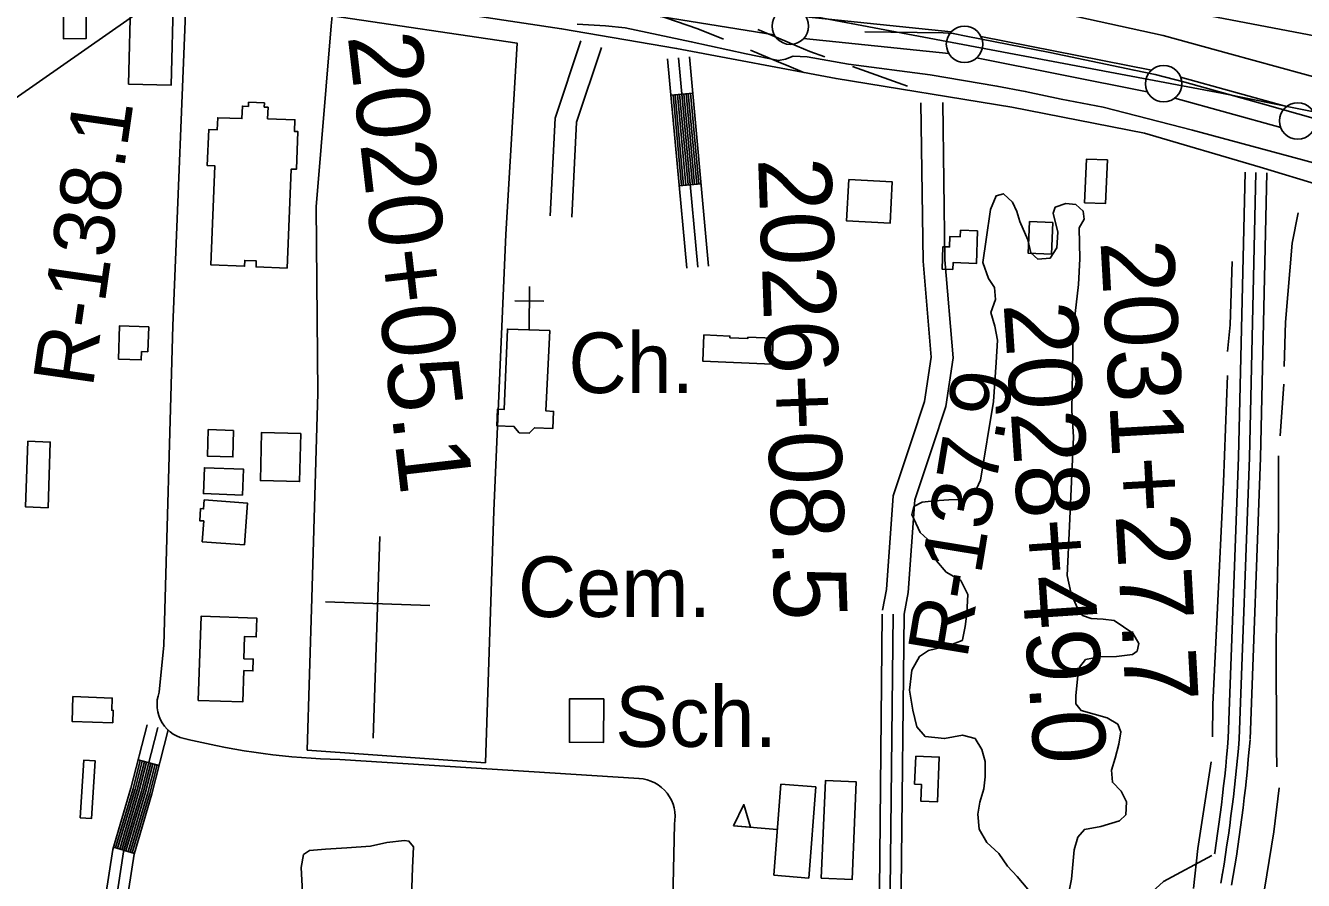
# Model space of a CAD drawing. Extents: x 3508733 to 3546731, y 546897 to 572481.
# Drawn here: x 3525316 to 3527070, y 561862 to 563035 of the extents above; entities that cross this region are included whole.
import ezdxf

# ---------------------------------------------------------------- set-up
doc = ezdxf.new("R2010")
doc.units = 0
for name, color, linetype in [('V-BLDG-IDEN', 7, 'Continuous'), ('V-BLDG-OTLN', 7, 'Continuous'), ('V-FLOD-BASE', 7, 'Continuous'), ('V-LEVE-TOET', 7, 'Continuous'), ('V-RIVR-FERY', 7, 'Continuous'), ('V-RIVR-RANG-IDEN', 7, 'Continuous'), ('V-ROAD-CNTR', 7, 'Continuous'), ('V-RRAP-FSHR', 7, 'Continuous'), ('V-SITE-OTLN', 7, 'Continuous'), ('V-SITE-OTLN-IDEN', 7, 'Continuous'), ('V-SITE-VEGE', 7, 'Continuous'), ('V-SURV-IDEN', 7, 'Continuous'), ('V-SURV-LINE', 7, 'Continuous'), ('V-TOPO-MINR', 7, 'Continuous'), ('V-TOPO-SHOR', 7, 'Continuous')]:
    doc.layers.add(name, color=color, linetype=linetype)

msp = doc.modelspace()

# ---------------------------------------------------------------- linework, layer by layer
at = {"layer": 'V-BLDG-OTLN'}
msp.add_line((3526347.4, 561932.5), (3526287.6, 561937.4), dxfattribs=at)
for points in [[(3525398.1, 563093.9), (3525398.9, 563017.6), (3525367.5, 563017.3), (3525367.4, 563093.6)], [(3525456.8, 562955.1), (3525459.9, 563080.7), (3525518.7, 563079.2), (3525515.6, 562953.7)], [(3525674.6, 562702.5), (3525632, 562704.2), (3525632.3, 562712.4), (3525616.4, 562713.1), (3525616.1, 562705.1), (3525570, 562706.9), (3525575.4, 562842.8), (3525565, 562843.2), (3525567, 562892.7), (3525578.6, 562892.3), (3525579.3, 562908.9), (3525612.6, 562907.6), (3525613.3, 562924.8), (3525621.5, 562924.5), (3525621.8, 562930.2), (3525643.5, 562929.3), (3525643.2, 562923.4), (3525648.4, 562923.2), (3525647.8, 562907.5), (3525685.4, 562906), (3525684.7, 562890), (3525689.4, 562889.8), (3525687.3, 562838.1), (3525680.1, 562838.3)], [(3526800.7, 562851), (3526798, 562791), (3526769.5, 562792.3), (3526772.2, 562852.2)], [(3526445.7, 562824.1), (3526505.4, 562820.9), (3526502.4, 562764), (3526442.7, 562767.2)], [(3526694, 562766.4), (3526725.8, 562765.1), (3526723.9, 562721.6), (3526692.1, 562722.9)], [(3526622.6, 562753.6), (3526621.1, 562709), (3526588.8, 562710.1), (3526588.5, 562700.7), (3526573.8, 562701.2), (3526574.9, 562731.9), (3526584.1, 562731.6), (3526584.6, 562746.1), (3526598.8, 562745.6), (3526599.1, 562754.4)], [(3525442.9, 562577.7), (3525444.7, 562623.4), (3525484.6, 562621.9), (3525483.3, 562587.7), (3525474.7, 562588.1), (3525474.3, 562576.5)], [(3526035.2, 562616.9), (3526030, 562506.5), (3526040.4, 562506), (3526039.3, 562482.3), (3526014, 562483.5), (3526007.1, 562475.9), (3525993.3, 562476.7), (3525986, 562485.4), (3525962.5, 562486.2), (3525963.4, 562509), (3525972.8, 562508.7), (3525977, 562618.9)], [(3526340.3, 562570.6), (3526245.1, 562574.9), (3526246.8, 562610.9), (3526282.6, 562609.3), (3526282.5, 562606.9), (3526307, 562605.8), (3526307.1, 562607.7), (3526341.9, 562606.2)], [(3525601.2, 562479.9), (3525600.1, 562443.4), (3525565.3, 562444.5), (3525566.4, 562481)], [(3525346.4, 562373.8), (3525315.6, 562374.8), (3525318.7, 562465), (3525349.5, 562463.9)], [(3525693.4, 562475.6), (3525691.7, 562409.6), (3525637.9, 562411), (3525639.6, 562477)], [(3525613.4, 562391.1), (3525559.7, 562393.2), (3525561.1, 562428.7), (3525614.8, 562426.6)], [(3525616.1, 562323), (3525558, 562327.2), (3525560.1, 562355.6), (3525554.7, 562356), (3525555.9, 562372.5), (3525559.9, 562372.2), (3525560.8, 562384.5), (3525620.2, 562380.2)], [(3525552.5, 562109.5), (3525556.5, 562224.9), (3525633.2, 562222.2), (3525632.3, 562196.6), (3525616.3, 562197.1), (3525615.3, 562166.6), (3525628.2, 562166.1), (3525627.6, 562149.8), (3525615.3, 562150.3), (3525613.8, 562107.4)], [(3525435.3, 562078.5), (3525379.3, 562080.6), (3525380.6, 562114.6), (3525434.5, 562112.6), (3525433.9, 562095.8), (3525435.9, 562095.7)], [(3526109.2, 562111.6), (3526109.1, 562051.8), (3526062.2, 562051.9), (3526062.3, 562111.7)], [(3525390.3, 561948.3), (3525395.5, 562027.3), (3525411.1, 562026.3), (3525405.9, 561947.2)], [(3526537.6, 562033.1), (3526569.9, 562031.7), (3526567.3, 561970.2), (3526544.4, 561971.2), (3526545.4, 561994.2), (3526536, 561994.6)], [(3526342.7, 561869.4), (3526352.4, 561994.4), (3526400.4, 561990.7), (3526390.8, 561865.7)], [(3526407.9, 561865.3), (3526413.6, 561999.3), (3526455.9, 561997.5), (3526450.2, 561863.5)], [(3526287.6, 561937.4), (3526301.5, 561966.4), (3526310.6, 561935.5)]]:
    msp.add_lwpolyline(points, close=True, dxfattribs=at)
at = {"layer": 'V-FLOD-BASE'}
msp.add_lwpolyline([(3527162.6, 562885.9), (3527013.7, 562927.8), (3526907.1, 562957.7), (3526866.1, 562968.4), (3526837.3, 562974.1), (3526721.8, 562998.6), (3526606.9, 563021), (3526589.1, 563024.6), (3526575.4, 563025.5), (3526467.8, 563026.6)], dxfattribs=at)
at = {"layer": 'V-LEVE-TOET'}
for points in [[(3526716.1, 563056.9), (3526877.5, 563021.7), (3526969, 562996.7), (3527068.8, 562969), (3527161.7, 562944.1)], [(3527188.4, 562818.6), (3527051.7, 562855.6), (3526917.7, 562892), (3526794.7, 562923.4), (3526737.3, 562934.2), (3526688, 562945), (3526649, 562952.2), (3526557.4, 562967.6), (3526445.1, 562982.4), (3526388.4, 562992.6), (3526369.1, 562993.3), (3526358.8, 562989.3), (3526349.2, 562987.4), (3526304.7, 562996.7), (3526229.5, 563013.2), (3526138.6, 563032), (3526111.9, 563035), (3526072.8, 563037.4)]]:
    msp.add_lwpolyline(points, dxfattribs=at)
at = {"layer": 'V-RIVR-FERY'}
msp.add_lwpolyline([(3524970.1, 562704.4), (3528560.1, 565210.4)], dxfattribs=at)
at = {"layer": 'V-ROAD-CNTR'}
for p, q in [((3526450.7, 562979.3), (3526526.1, 562952.2)), ((3526231.4, 562942.7), (3526201.5, 562940)), ((3526242.9, 562818.3), (3526213, 562815.5)), ((3525499.1, 562020.3), (3525470, 562027.7)), ((3525464.9, 561899.5), (3525436.2, 561908))]:
    msp.add_line(p, q, dxfattribs=at)
for points in [[(3527459.7, 562715.9), (3527179.9, 562790), (3527010.3, 562841.2), (3526851.7, 562887.6), (3526669.4, 562923.3), (3526428.3, 562962.7), (3526209.3, 563003.9), (3526051.5, 563030.9), (3525817.1, 563066.2), (3525532, 563111)], [(3525537.4, 563109.3), (3525517.5, 562623.4), (3525505.4, 562185.3), (3525498.9, 562120.6)], [(3526180, 563051), (3526238.5, 563030.7), (3526273.9, 563016.8)], [(3526320.6, 563030.1), (3526358, 563014.3), (3526374.9, 563007.1), (3526392.4, 562999.7), (3526413, 562992.6)], [(3526077.6, 563014.5), (3526042.4, 562908.3), (3526035.5, 562774.1)], [(3526106.1, 563005.1), (3526072.1, 562902.7), (3526065.5, 562772.5)], [(3526196.9, 562989.8), (3526223.4, 562702.6)], [(3526211.9, 562991.1), (3526238.4, 562704)], [(3526226.8, 562992.5), (3526253.3, 562705.3)], [(3526310.7, 563001.7), (3526346.4, 562986.6), (3526363.2, 562979.5), (3526381.6, 562971.7), (3526383.3, 562971.1)], [(3526204.5, 562940.2), (3526216, 562815.8)], [(3526207.5, 562940.5), (3526219, 562816.1)], [(3526210.5, 562940.8), (3526222, 562816.3)], [(3526213.5, 562941.1), (3526225, 562816.6)], [(3526216.5, 562941.4), (3526227.9, 562816.9)], [(3526219.4, 562941.6), (3526230.9, 562817.2)], [(3526222.4, 562941.9), (3526233.9, 562817.4)], [(3526225.4, 562942.2), (3526236.9, 562817.7)], [(3526228.4, 562942.5), (3526239.9, 562818)], [(3526544.8, 562929.4), (3526547.6, 562712.2), (3526559, 562580.3), (3526549.5, 562519.7), (3526531.6, 562465.4), (3526506.6, 562390.3), (3526497.4, 562261.4), (3526492, 562233.2)], [(3526574.8, 562929.8), (3526577.6, 562713.7), (3526589.2, 562579.3), (3526578.8, 562512.6), (3526560.1, 562456), (3526536.3, 562384.4), (3526527.2, 562257.6), (3526521.5, 562227.6)], [(3526989.7, 562834.1), (3526980.7, 562443), (3526966.6, 562057.3)], [(3527004.7, 562833.7), (3526995.7, 562442.5), (3526981.6, 562056.8)], [(3527019.7, 562833.4), (3527010.7, 562442.1), (3526996.6, 562056.2)], [(3526491.5, 562227.9), (3526487.7, 561848.4), (3526504.1, 561755.6), (3526479.9, 561326.3), (3526670.3, 561312.4), (3526693.8, 561308.9), (3526712.1, 561293.8)], [(3526506.5, 562227.8), (3526502.7, 561849.6), (3526519.2, 561756.5), (3526495.7, 561340.2), (3526671.9, 561327.3), (3526700.2, 561323.1), (3526731, 561297.6)], [(3526521.5, 562227.6), (3526517.7, 561850.9), (3526534.3, 561757.4), (3526511.5, 561354), (3526614.1, 561346.5)], [(3525482.3, 562076.1), (3525460.2, 561988.9), (3525435.3, 561905), (3525420.2, 561807.5), (3525409.2, 561645.6), (3525392, 561184.9), (3525372.2, 560681.9), (3525357.6, 560233.9)], [(3525496.9, 562072.4), (3525474.6, 561985), (3525449.9, 561901.7), (3525435.2, 561805.8), (3525424.1, 561644.8), (3525407, 561184.4), (3525387.1, 560681.4), (3525372.6, 560233.4)], [(3525511.4, 562068.8), (3525489.1, 561981), (3525464.6, 561898.4), (3525450.1, 561804.2), (3525439.1, 561644), (3525422, 561183.8), (3525402.1, 560680.8), (3525387.6, 560232.9)], [(3526966.7, 562058), (3526965.6, 562044.8), (3526964.4, 562031.6), (3526963.1, 562018.5), (3526961.8, 562005.3), (3526960.3, 561992.2), (3526958.8, 561979), (3526957.2, 561965.9), (3526955.6, 561952.8), (3526953.8, 561939.7), (3526952, 561926.6), (3526950.1, 561913.5), (3526948.1, 561900.4), (3526947.9, 561899.1)], [(3526981.6, 562056.8), (3526980.5, 562043.5), (3526979.3, 562030.2), (3526978, 562017), (3526976.7, 562003.7), (3526975.2, 561990.5), (3526973.7, 561977.3), (3526972.1, 561964), (3526970.4, 561950.8), (3526968.7, 561937.6), (3526966.8, 561924.4), (3526964.9, 561911.3), (3526962.9, 561898.1), (3526960.9, 561884.9), (3526958.7, 561871.8), (3526956.5, 561858.7)], [(3526996.6, 562055.5), (3526995.4, 562042.2), (3526994.2, 562028.8), (3526993, 562015.5), (3526991.6, 562002.2), (3526990.1, 561988.8), (3526988.6, 561975.5), (3526987, 561962.2), (3526985.3, 561948.9), (3526983.5, 561935.6), (3526981.7, 561922.3), (3526979.8, 561909.1), (3526977.8, 561895.8), (3526975.7, 561882.6), (3526973.5, 561869.3), (3526971.3, 561856.1)], [(3525472.9, 562026.9), (3525463.1, 561988.2), (3525439, 561907.1)], [(3525475.8, 562026.2), (3525466, 561987.4), (3525441.9, 561906.3)], [(3525478.7, 562025.5), (3525468.9, 561986.6), (3525444.8, 561905.4)], [(3525481.6, 562024.7), (3525471.7, 561985.8), (3525447.7, 561904.6)], [(3525484.6, 562024), (3525474.6, 561985), (3525450.5, 561903.7)], [(3525487.5, 562023.3), (3525477.5, 561984.2), (3525453.4, 561902.9)], [(3525490.4, 562022.5), (3525480.4, 561983.4), (3525456.3, 561902)], [(3525747, 562028.3), (3526157.7, 562002.2)], [(3525493.3, 562021.8), (3525483.3, 561982.6), (3525459.2, 561901.2)], [(3525496.2, 562021), (3525486.2, 561981.8), (3525462.1, 561900.3)], [(3526206.2, 561939.5), (3526193.4, 561358.8), (3526177.8, 560724.9)], [(3526944, 561896.4), (3526877.9, 561860.9), (3526811.7, 561801.2), (3526762.1, 561734.8), (3526714.7, 561611.5), (3526705.7, 561513.1), (3526695.2, 561438.9), (3526666.7, 561400.7), (3526616.3, 561347.6)], [(3526958.2, 561870), (3526957.2, 561869.4)]]:
    msp.add_lwpolyline(points, dxfattribs=at)
for centre, radius, start, end in [((3525544.3, 562103.9), 48.3, 159.7838, 263.1784), ((3525771.3, 563013.2), 985.2, 256.3192, 268.5851), ((3526154.9, 561949.9), 52.4, 348.4996, 86.9598)]:
    msp.add_arc(centre, radius, start, end, dxfattribs=at)
at = {"layer": 'V-RRAP-FSHR'}
msp.add_lwpolyline([(3523475.5, 563626.1), (3524086.4, 563502.4), (3525193.3, 563274.6), (3526957.5, 562942.6), (3528202.6, 562690.4), (3529085.9, 562552.3), (3529836.5, 562463.4), (3529988.5, 562444.1), (3530121.4, 562433.3), (3530591.9, 562422.1), (3531229.9, 562384.2)], dxfattribs=at)
at = {"layer": 'V-SITE-OTLN'}
for p, q in [((3526006.7, 562617.4), (3526007.2, 562677.4)), ((3526027, 562657.3), (3525987, 562657.6)), ((3525792.7, 562057.8), (3525802.1, 562334.5)), ((3525870.5, 562239.8), (3525727.5, 562244.7))]:
    msp.add_line(p, q, dxfattribs=at)
msp.add_lwpolyline([(3525734.9, 563034.9), (3525736.4, 563048.7), (3525990.5, 563011.1), (3525974.8, 562748.5), (3525958.6, 562369.4), (3525946.9, 562023.8), (3525702.2, 562041.3), (3525708.4, 562249.8), (3525716.8, 562531), (3525714.6, 562786.8)], close=True, dxfattribs=at)
at = {"layer": 'V-SITE-VEGE'}
for points in [[(3526691.6, 561850.3), (3526676.7, 561867.6), (3526663.8, 561882.1), (3526651.6, 561899.4), (3526635.3, 561914.6), (3526624.6, 561932.6), (3526622.7, 561953.1), (3526625.6, 561969.6), (3526631.3, 561988), (3526632.8, 562004.4), (3526633, 562025.7), (3526628.4, 562042.2), (3526619, 562057.3), (3526601.9, 562061.6), (3526577.2, 562057.1), (3526550.5, 562060.1), (3526539, 562073.2), (3526533.7, 562095.9), (3526529.2, 562123.4), (3526532.2, 562150.7), (3526542.7, 562169.8), (3526555.1, 562177.9), (3526581.9, 562184.5), (3526601.2, 562191.8), (3526601.9, 562192.5), (3526605.5, 562211), (3526607.7, 562228.8), (3526609.3, 562254.8), (3526599.3, 562274.1), (3526579.5, 562285.2), (3526566, 562301.1), (3526558.7, 562325.9), (3526543.7, 562339.7), (3526532.3, 562364.5), (3526535.2, 562375.5), (3526546.2, 562381.5), (3526562.7, 562383.4), (3526583.2, 562384.6), (3526603.1, 562385.1), (3526618.3, 562393.8), (3526626.7, 562411.5), (3526644.2, 562519.6), (3526648.2, 562573), (3526649.9, 562603.9), (3526646, 562623.1), (3526640.7, 562641.6), (3526647, 562659.4), (3526645.8, 562675.9), (3526637.7, 562688.3), (3526629.7, 562710.3), (3526634.2, 562741.8), (3526640.1, 562782.8), (3526647.8, 562801.9), (3526658.1, 562804.6), (3526670.3, 562792.8), (3526676.4, 562780.4), (3526680.3, 562766.6), (3526691.7, 562741.2), (3526695.7, 562723.3)], [(3526695.7, 562723.3), (3526705.2, 562715), (3526722.3, 562716.2), (3526731.4, 562730.5), (3526732.9, 562751.7), (3526726.4, 562777.8), (3526729.2, 562786), (3526743.6, 562791.4), (3526757.3, 562789.8), (3526767.5, 562780.8), (3526768.8, 562769.9), (3526761.8, 562757.6), (3526762.7, 562715.1), (3526761, 562680.2), (3526753.5, 562616.5), (3526751.7, 562506.9), (3526754.1, 562471.2)], [(3526754.1, 562471.2), (3526748.7, 562348.6), (3526745.3, 562280.8), (3526751.2, 562255.4), (3526759.9, 562236.1), (3526766.7, 562225.8), (3526778.3, 562221.6), (3526794.7, 562220.7), (3526809.8, 562219.2), (3526835.6, 562201.8), (3526843.7, 562187.3), (3526841.5, 562177.1), (3526835.3, 562172.3), (3526813.4, 562169.8), (3526790.1, 562169.4), (3526770.8, 562165.4), (3526762.5, 562155.2), (3526760.4, 562147.7), (3526757.3, 562116.2), (3526757.2, 562104.6), (3526764.6, 562095.6), (3526800.2, 562085.6), (3526815.2, 562076.6), (3526819.2, 562066.3), (3526816.2, 562049.2), (3526811.3, 562030), (3526806.3, 562013.6), (3526807.5, 561997.2), (3526819.7, 561984.7), (3526827.1, 561970.3), (3526826.2, 561952.4), (3526817.2, 561944.3), (3526791.8, 561936.3), (3526769.1, 561932.5), (3526760.1, 561921.6), (3526755.2, 561904.5), (3526751.3, 561864.1), (3526745.5, 561834.7)], [(3525695.8, 561845.8), (3525694.1, 561880.1), (3525697.1, 561897.9), (3525705.3, 561903.3), (3525727.3, 561905.1), (3525756.8, 561906.9), (3525789, 561909.3), (3525811.7, 561914.5), (3525835.7, 561917), (3525841.8, 561916.3), (3525847.9, 561908.7), (3525846.9, 561879.9), (3525841, 561702.5)]]:
    msp.add_lwpolyline(points, dxfattribs=at)
at = {"layer": 'V-SURV-LINE'}
for points in [[(3526343.3, 563022.8), (3525921.8, 563090.8)], [(3526386.8, 563047.3), (3526586.3, 563026.7)], [(3526583.2, 562996.8), (3526383.7, 563017.5)], [(3526627.1, 563020.5), (3526861.2, 562974.1)], [(3526855.4, 562944.6), (3526621.2, 562991.1)], [(3526901.2, 562964.6), (3527046.7, 562924.3)], [(3527038.7, 562895.4), (3526893.2, 562935.7)]]:
    msp.add_lwpolyline(points, dxfattribs=at)
for centre in [(3526365.4, 563034.5), (3526604.6, 563009.7), (3526877.9, 562955.5), (3527062, 562904.5)]:
    msp.add_circle(centre, 25, dxfattribs=at)
at = {"layer": 'V-TOPO-MINR'}
msp.add_lwpolyline([(3525259.6, 563338.2), (3525319.2, 563331.7), (3525378.6, 563324.2), (3525489.6, 563309.1), (3525493.5, 563308.6), (3525497.4, 563308), (3525501.3, 563307.4), (3525505.2, 563306.8), (3525558.3, 563298.5), (3525588.7, 563293.6), (3525619, 563288.6), (3525649.4, 563283.4), (3525679.7, 563278), (3526658.5, 563102.9), (3526663.2, 563102), (3526667.9, 563101.2), (3526672.6, 563100.3), (3526677.3, 563099.4), (3526718, 563091.7), (3526743.1, 563086.9), (3526768.2, 563082.1), (3526793.2, 563077.3), (3526818.3, 563072.5), (3527772.4, 562890.3)], dxfattribs=at)
at = {"layer": 'V-TOPO-SHOR'}
msp.add_line((3527042.9, 562543.5), (3527038.1, 562472.4), dxfattribs=at)
for points in [[(3527062.4, 562778.3), (3527054.5, 562736.7), (3527045.2, 562628.2), (3527043.2, 562567.4)], [(3526972.2, 562711.6), (3526969.3, 562624.8), (3526965.5, 562588)], [(3526965.8, 562555.2), (3526960.2, 562409), (3526951.6, 562226.6), (3526945.5, 562103.7), (3526945.1, 562059.3)], [(3527035.8, 562445.1), (3527035.5, 562350.1), (3527032.5, 562190.3), (3527033.1, 562043.3), (3527033.5, 562018.1)], [(3526943.4, 562025.1), (3526925.1, 561906.4), (3526919, 561851.1)], [(3527036.6, 561989.3), (3527029.2, 561929.3), (3527010.2, 561811.2), (3526991, 561736.9)]]:
    msp.add_lwpolyline(points, dxfattribs=at)

# ---------------------------------------------------------------- texts
at = {"layer": 'V-BLDG-IDEN'}
msp.add_text('Sch.', height=83, dxfattribs=at).set_placement((3526125, 562045.7))
at = {"layer": 'V-RIVR-RANG-IDEN'}
for s, rotation, p in [('R-138.1', 81.8463, (3525407.6, 562537.2)), ('R-137.9', 80.615, (3526608, 562164.7))]:
    msp.add_text(s, height=83, rotation=rotation, dxfattribs=at).set_placement(p)
at = {"layer": 'V-SITE-OTLN-IDEN'}
for s, p in [('Ch.', (3526060.7, 562531.1)), ('Cem.', (3525991.4, 562223.8))]:
    msp.add_text(s, height=83, dxfattribs=at).set_placement(p)
at = {"layer": 'V-SURV-IDEN'}
for s, rotation, p in [('2020+05.1', 276.6307, (3525757.7, 563021.2)), ('2026+08.5', 272.1048, (3526321.1, 562853)), ('2031+27.7', 273.1589, (3526791.2, 562739.1)), ('2028+49.0', 273.8103, (3526658.2, 562653.6))]:
    msp.add_text(s, height=100, rotation=rotation, dxfattribs=at).set_placement(p)

doc.saveas('drawing.dxf')
